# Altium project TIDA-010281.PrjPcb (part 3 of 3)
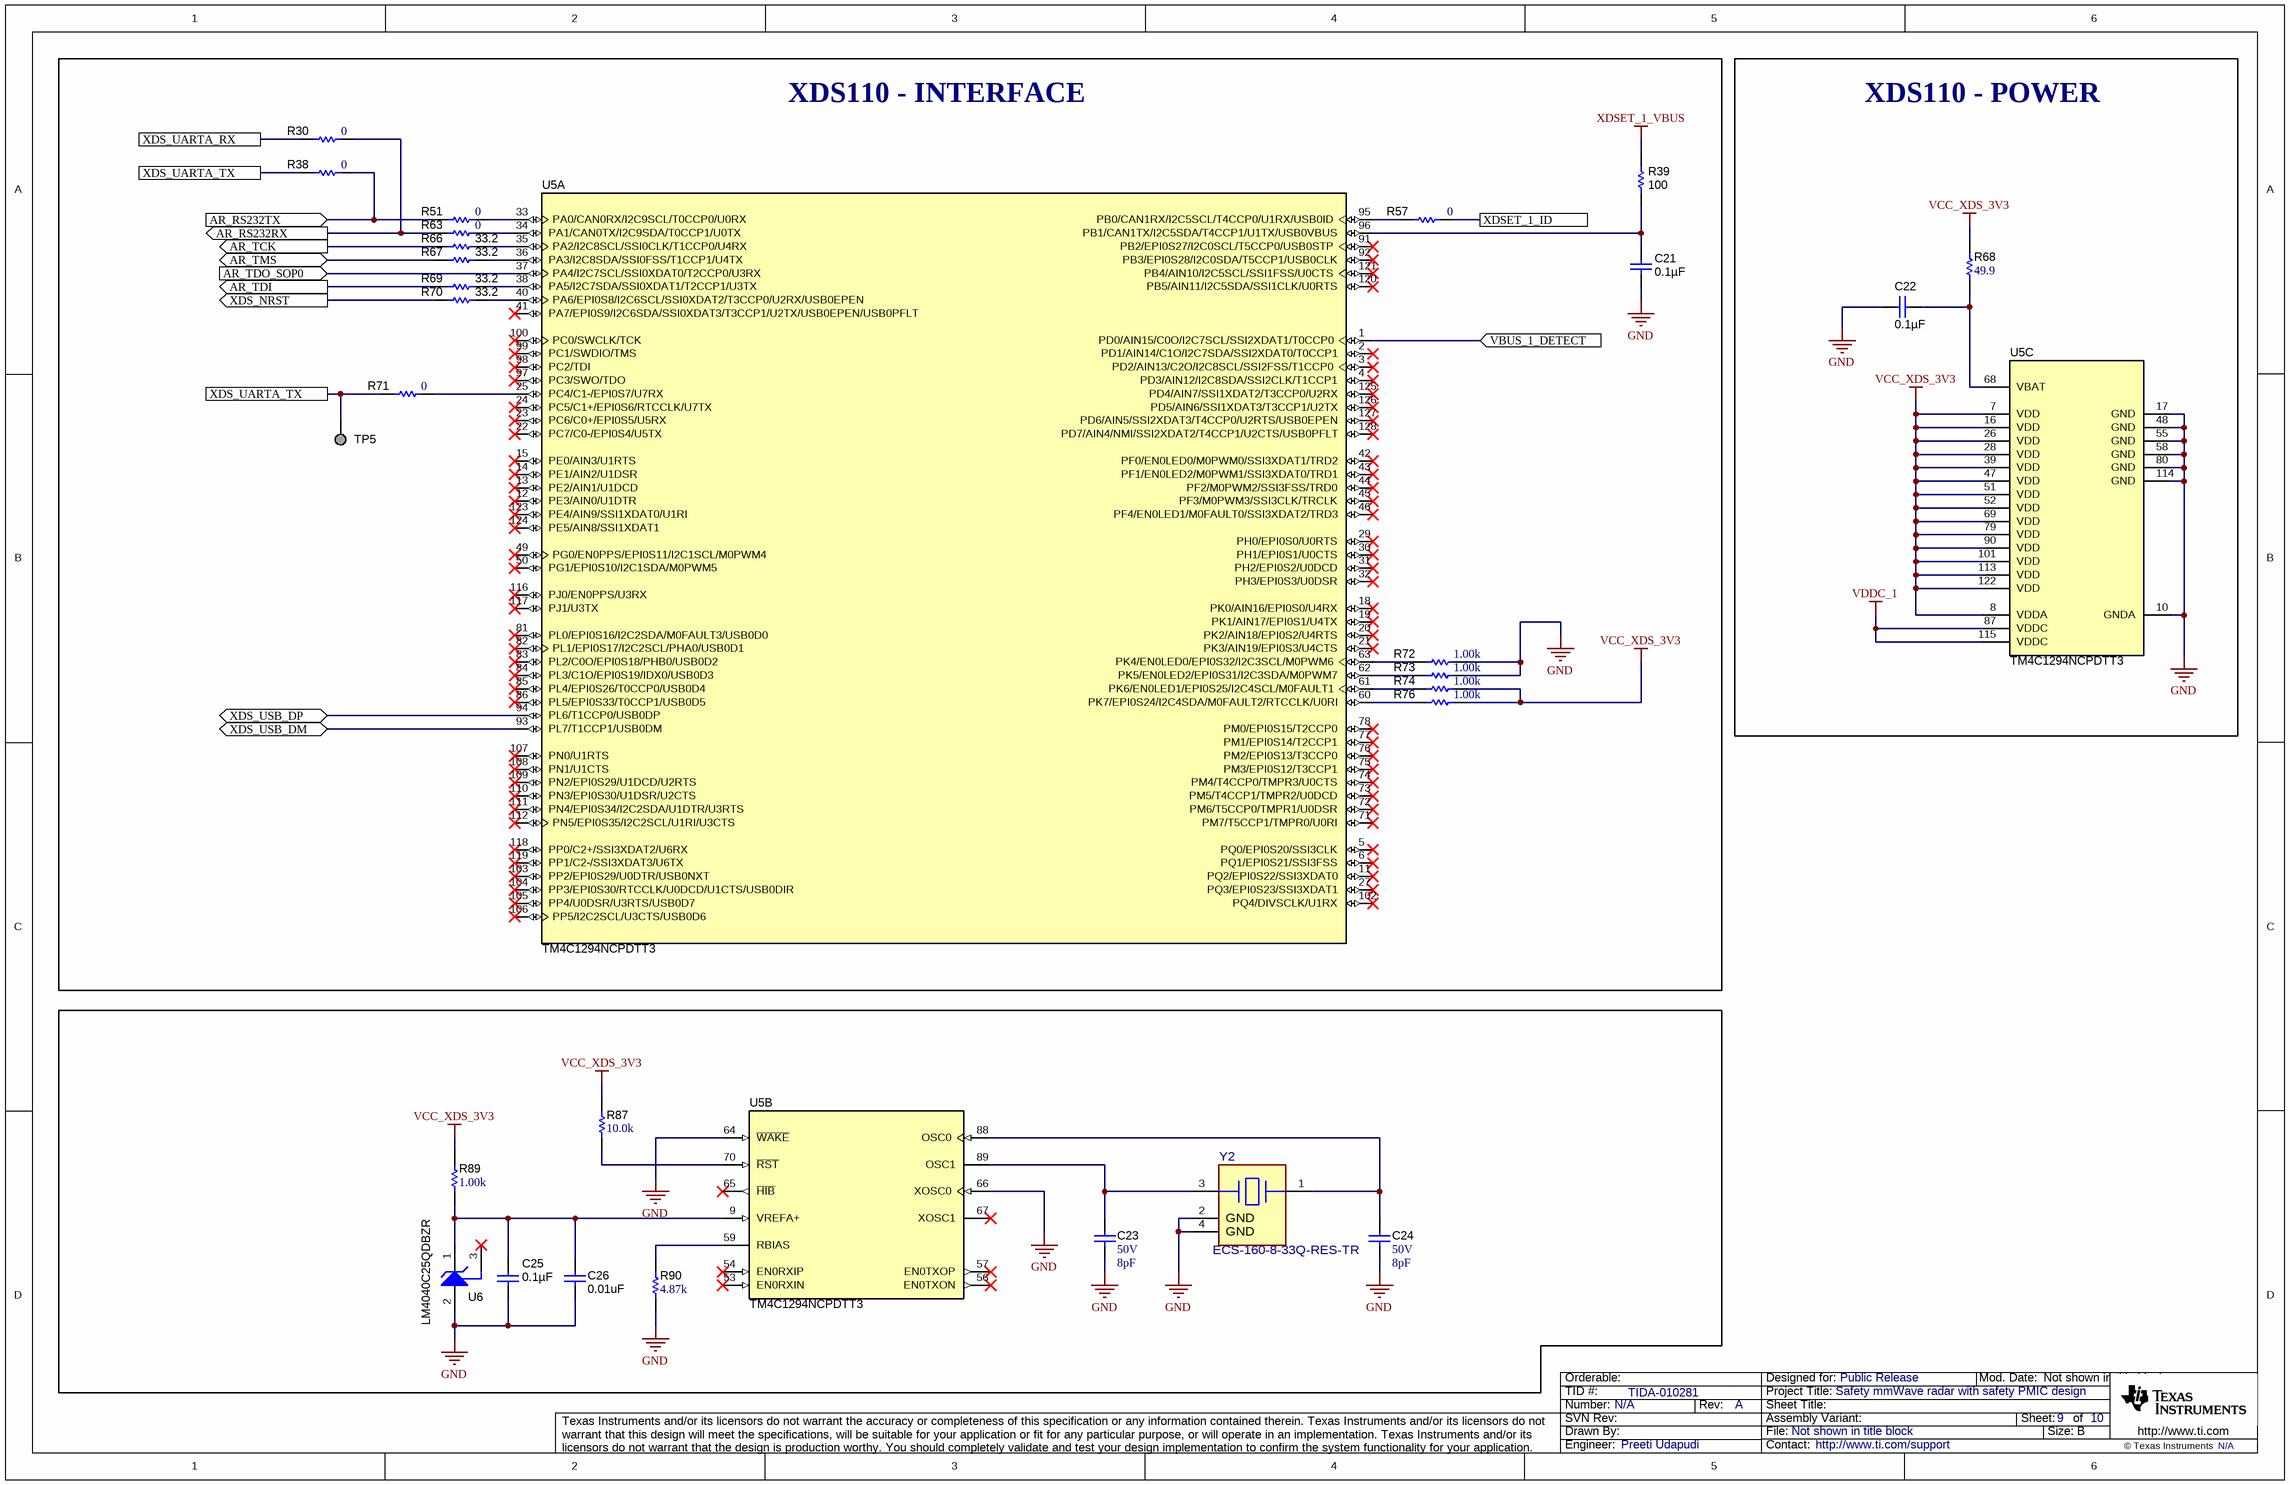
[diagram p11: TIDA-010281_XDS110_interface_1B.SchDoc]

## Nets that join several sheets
5V_IN: TIDA-010281_FLASH_USB_SOP (C1.2 C4.1 D1.1 R64.1), TIDA-010281_PMIC_BUCK (C118.2 C127.2 L1.1 R105.1), TIDA-010281_RST_SWITCH (R107.1), TIDA-010281_XDS110_interface_1A (R1.1)
AR_1P0_RF2: TIDA-010281_AOP_PWR (22 pins), TIDA-010281_PMIC_BUCK (C86.2 C93.2 L9.2 R126.2)
AR_1P2: TIDA-010281_AOP_PWR (19 pins), TIDA-010281_PMIC_BUCK (C99.2 C104.2 L10.2 R128.2)
AR_1V8: TIDA-010281_AOP_PWR (26 pins), TIDA-010281_PMIC_BUCK (C54.2 C77.2 L7.2 R121.2)
AR_VBGAP: TIDA-010281_AOP_IO (U2.A16), TIDA-010281_AOP_PWR (C69.1)
GND: TIDA-010281_AOP_IO (11 pins), TIDA-010281_AOP_PWR (116 pins), TIDA-010281_FLASH_USB_SOP (17 pins), TIDA-010281_PMIC_BUCK (55 pins), TIDA-010281_RST_SWITCH (15 pins), TIDA-010281_XDS110_interface_1A (19 pins), TIDA-010281_XDS110_interface_1B (21 pins)
PMIC_3V3: TIDA-010281_AOP_IO (10 pins), TIDA-010281_AOP_PWR (5 pins), TIDA-010281_FLASH_USB_SOP (6 pins), TIDA-010281_PMIC_BUCK (5 pins)
VCC_BA_3V3: TIDA-010281_FLASH_USB_SOP (R16.1), TIDA-010281_PMIC_BUCK (L12.2 R104.2 TP16.1), TIDA-010281_RST_SWITCH (12 pins)
VCC_XDS_3V3: TIDA-010281_XDS110_interface_1A (11 pins), TIDA-010281_XDS110_interface_1B (20 pins)
VDDC_1: TIDA-010281_XDS110_interface_1A (C17.2 C18.2 C19.2 C20.1), TIDA-010281_XDS110_interface_1B (U5.87 U5.115)
XDSET_1_VBUS: TIDA-010281_XDS110_interface_1A (R17.2), TIDA-010281_XDS110_interface_1B (R39.2)
AR_CS1: TIDA-010281_AOP_IO (R9.2 U2.C2), TIDA-010281_PMIC_BUCK (R91.1)
AR_GPIO_1: TIDA-010281_AOP_IO (U2.L3), TIDA-010281_RST_SWITCH (R129.2)
AR_GPIO_2: TIDA-010281_AOP_IO (U2.K3), TIDA-010281_RST_SWITCH (LD3.1)
AR_MISO1: TIDA-010281_AOP_IO (U2.D1), TIDA-010281_PMIC_BUCK (R139.1)
AR_MOSI1: TIDA-010281_AOP_IO (U2.F2), TIDA-010281_PMIC_BUCK (R136.2)
AR_NERR_OUT: TIDA-010281_AOP_IO (R21.1 U2.U15), TIDA-010281_PMIC_BUCK (R94.1)
AR_NRST: TIDA-010281_AOP_IO (C130.1 R59.1 TP14.1 U2.U11), TIDA-010281_RST_SWITCH (R108.1 U16.4)
AR_NRST_PMIC: TIDA-010281_PMIC_BUCK (R95.1), TIDA-010281_RST_SWITCH (R178.2 U16.3)
AR_QSPI_CLK: TIDA-010281_AOP_IO (U2.H2), TIDA-010281_FLASH_USB_SOP (R47.1)
AR_QSPI_CS: TIDA-010281_AOP_IO (U2.J2), TIDA-010281_FLASH_USB_SOP (R43.1 U9.1)
AR_QSPI_D0: TIDA-010281_AOP_IO (U2.H3), TIDA-010281_FLASH_USB_SOP (R6.1)
AR_QSPI_D1: TIDA-010281_AOP_IO (U2.G2), TIDA-010281_FLASH_USB_SOP (R46.1)
AR_QSPI_D2: TIDA-010281_AOP_IO (U2.J3), TIDA-010281_FLASH_USB_SOP (R44.1 R48.1)
AR_QSPI_D3: TIDA-010281_AOP_IO (U2.K2), TIDA-010281_FLASH_USB_SOP (R45.1 R49.1)
AR_RS232RX: TIDA-010281_AOP_IO (R5.2 U2.V16), TIDA-010281_XDS110_interface_1B (R30.2 R63.1)
AR_RS232TX: TIDA-010281_AOP_IO (R4.2 U2.U16), TIDA-010281_XDS110_interface_1B (R38.2 R51.1)
AR_SPICLK1: TIDA-010281_AOP_IO (R75.2 U2.D2), TIDA-010281_PMIC_BUCK (R134.2)
AR_TCK: TIDA-010281_AOP_IO (U2.T3), TIDA-010281_XDS110_interface_1B (R66.2)
AR_TDI: TIDA-010281_AOP_IO (U2.U9), TIDA-010281_XDS110_interface_1B (R69.2)
AR_TDO_SOP0: TIDA-010281_AOP_IO (R83.1 U2.U10), TIDA-010281_XDS110_interface_1B (U5.37)
AR_TMS: TIDA-010281_AOP_IO (U2.U8), TIDA-010281_XDS110_interface_1B (R67.2)
PGOOD: TIDA-010281_PMIC_BUCK (R106.1 R112.2 R118.1 R119.2), TIDA-010281_XDS110_interface_1A (R18.1)
PMIC_CLK: TIDA-010281_AOP_IO (R103.2), TIDA-010281_PMIC_BUCK (R127.1)
SOP0: TIDA-010281_AOP_IO (R159.2), TIDA-010281_FLASH_USB_SOP (S1.3)
SOP1: TIDA-010281_AOP_IO (R171.2), TIDA-010281_FLASH_USB_SOP (S1.4)
USB_DM: TIDA-010281_FLASH_USB_SOP (J1.2), TIDA-010281_XDS110_interface_1B (U5.93)
USB_DP: TIDA-010281_FLASH_USB_SOP (J1.3), TIDA-010281_XDS110_interface_1B (U5.94)
VBUS_1_DETECT: TIDA-010281_XDS110_interface_1A (C16.2 R17.1 R29.2), TIDA-010281_XDS110_interface_1B (U5.1)
XDS_NRST: TIDA-010281_RST_SWITCH (R177.2 U16.1), TIDA-010281_XDS110_interface_1B (R70.2)

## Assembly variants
001: not fitted C38 C39 C73 C107 FID1 FID2 FID3 FID4 FID5 FID6 R30 R38 R77 R78 R80 R81 R82 R93 R94 R96 R97 R98 R103 R109 R120 R131 Y4
002: not fitted C38 C39 C73 FID1 FID2 FID3 FID4 FID5 FID6 R77 R78 R80 R81 R82 R93 R96 R98 R103 R109 Y4; alternate parts U2 -> CMP-0860942-3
